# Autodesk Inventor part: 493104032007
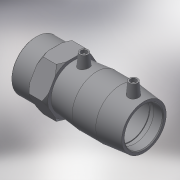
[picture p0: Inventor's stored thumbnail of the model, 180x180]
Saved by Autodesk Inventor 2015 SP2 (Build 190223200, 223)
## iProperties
Created: 2017-06
Part Number: 493104032007
Material: Generic
Description: PLASSON FEMALE TRANSITION COUPLER 32-3/4"
Document SubType Name: Modeling
Designer: KIM
Mass: 127.731 g
Surface Area: 321.398 cm^2
Volume: 127.731 cm^3
Density: 1 g/cm^3
Appearance: Default
Author: KIM
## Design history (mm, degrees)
derived "493104.ipt"
feature "Solid1::493104.ipt"
tag "TaggingFeature1"
body "Solid1"
other parameters: "d0" = 101, "d1" = 32, "d2" = 44, "d3" = 39, "d4" = 33.66667, "d5" = 39.6, "d6" = 30.4, "d7" = 32, "d8" = 168 deg, "d10" = 15.6, "d11" = 5.2, "d29" = 42, "d30" = 14, "d31" = 35.35, "d34" = 5 deg, "d41" = 4, "d42" = 14, "d43" = 0, "d48" = 3, "d49" = 0, "d55" = 23, "d57" = 19, "d59" = 24.117, "d60" = 20.7, "d70" = 44, "d71" = 11.5, "d72" = 0, "d73" = 45 deg, "d74" = 1.9, "d75" = 45 deg, "d77" = 0.48, "d80" = 0.64, "d_" = 32, "L_" = 124, "L_1" = 39, "D_1" = 44, "A_" = 42, "d_2" = 12, "L_2" = 23, "D_" = 19, "R_p" = 24.117
